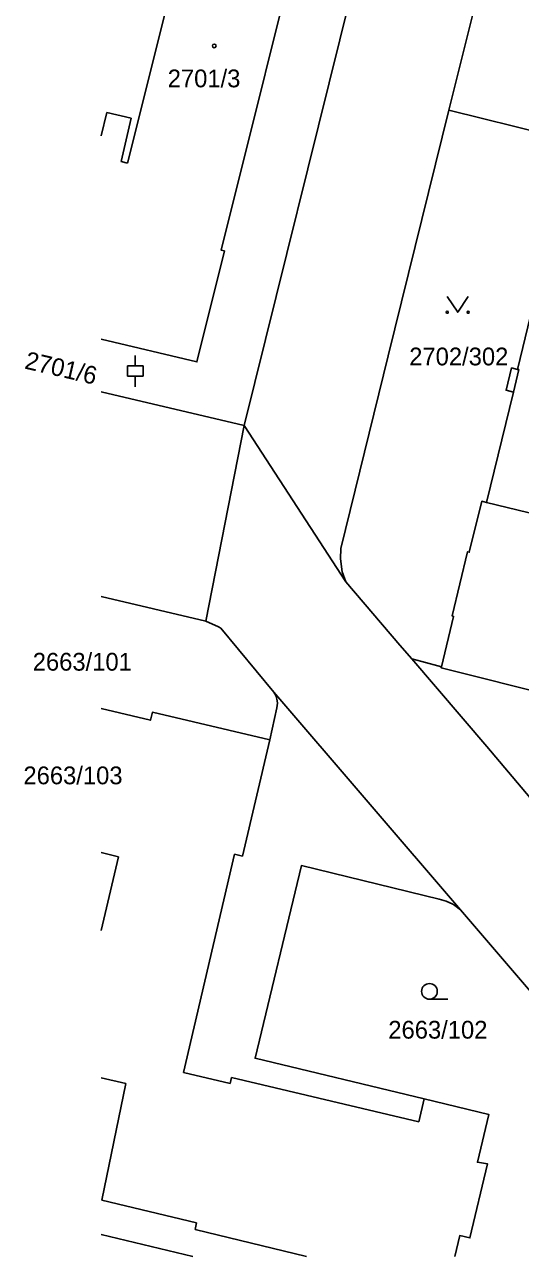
# Model space of a CAD drawing. Extents: x -496682 to -495776, y -1088797 to -1088018.
# Drawn here: x -496681.5 to -496634.1, y -1088569.4 to -1088451.6 of the extents above; entities that cross this region are included whole.
import ezdxf

# ---------------------------------------------------------------- set-up
doc = ezdxf.new("R2010")
doc.units = 0
for name, color, linetype in [('Hranice parcel', 7, 'Continuous'), ('Parcelní čísla', 7, 'Continuous'), ('Vnitřní kresba', 7, 'Continuous'), ('Značky budov', 7, 'Continuous'), ('Značky kultur', 7, 'Continuous')]:
    doc.layers.add(name, color=color, linetype=linetype)

msp = doc.modelspace()

# ---------------------------------------------------------------- linework, layer by layer
at = {"layer": 'Hranice parcel'}
for p, q in [((-496640.95, -1088459.81), (-496628.55, -1088409.94)), ((-496660.52, -1088489.98), (-496645.25, -1088428.29)), ((-496629.09, -1088462.74), (-496640.95, -1088459.81)), ((-496660.52, -1088489.98), (-496674.2, -1088486.74)), ((-496664.18, -1088508.68), (-496660.52, -1088489.98)), ((-496660.52, -1088489.98), (-496650.79, -1088504.94)), ((-496625.56, -1088500.2), (-496637.35, -1088497.34)), ((-496674.2, -1088506.32), (-496664.18, -1088508.68)), ((-496657.68, -1088515.47), (-496662.75, -1088509.37)), ((-496639.82, -1088536.3), (-496657.68, -1088515.47)), ((-496627.27, -1088550.98), (-496639.82, -1088536.3))]:
    msp.add_line(p, q, dxfattribs=at)
for points in [[(-496674.2, -1088481.71), (-496665.05, -1088483.89), (-496662.42, -1088473.27), (-496662.72, -1088473.21), (-496654.28, -1088439.31), (-496654, -1088439.38), (-496650.83, -1088426.78), (-496645.25, -1088428.29)], [(-496650.79, -1088504.94), (-496651.14, -1088503.97), (-496651.32, -1088502.72), (-496651.27, -1088501.75), (-496646.76, -1088483.31), (-496640.95, -1088459.81)], [(-496637.35, -1088497.34), (-496634.78, -1088486.77), (-496635.48, -1088486.6), (-496634.95, -1088484.46), (-496634.38, -1088484.6), (-496631.65, -1088473.31)], [(-496641.66, -1088513.05), (-496640.49, -1088508.23), (-496640.63, -1088508.19), (-496639.16, -1088502.05), (-496638.99, -1088502.09), (-496637.8, -1088497.21), (-496637.35, -1088497.34)], [(-496644.5, -1088512.3), (-496645.64, -1088510.97), (-496650.79, -1088504.94)], [(-496662.75, -1088509.37), (-496662.98, -1088509.24), (-496664.18, -1088508.68)], [(-496621.83, -1088538.93), (-496627.8, -1088531.94), (-496637.3, -1088520.68), (-496644.5, -1088512.3)], [(-496644.5, -1088512.3), (-496643.54, -1088512.55), (-496641.66, -1088513.05)], [(-496619.55, -1088518.48), (-496630.64, -1088516.04), (-496630.61, -1088515.92), (-496641.69, -1088513.15), (-496641.66, -1088513.05)], [(-496657.39, -1088516.99), (-496657.35, -1088516.54), (-496657.37, -1088516.31), (-496657.48, -1088515.87), (-496657.68, -1088515.47)], [(-496674.2, -1088517.05), (-496669.49, -1088518.17), (-496669.31, -1088517.4), (-496658.07, -1088520.03), (-496657.39, -1088516.99)], [(-496641.88, -1088535.27), (-496655.05, -1088532.06), (-496659.48, -1088550.5), (-496643.3, -1088554.38), (-496637.13, -1088555.87), (-496638.22, -1088560.45), (-496637.25, -1088560.61), (-496638.93, -1088567.68), (-496639.91, -1088567.46), (-496640.39, -1088569.45)], [(-496639.82, -1088536.3), (-496640.39, -1088535.89), (-496640.58, -1088535.77), (-496641.21, -1088535.48), (-496641.88, -1088535.27)], [(-496674.2, -1088567.37), (-496665.44, -1088569.45)]]:
    msp.add_lwpolyline(points, dxfattribs=at)
at = {"layer": 'Vnitřní kresba'}
for p, q in [((-496671.69, -1088464.87), (-496666.18, -1088442.82)), ((-496674.2, -1088462.26), (-496673.67, -1088460.03)), ((-496673.67, -1088460.03), (-496671.33, -1088460.58)), ((-496671.33, -1088460.58), (-496672.3, -1088464.73)), ((-496672.3, -1088464.73), (-496671.69, -1088464.87)), ((-496634.26, -1088484.62), (-496634.78, -1088486.77)), ((-496634.38, -1088484.6), (-496634.26, -1088484.62)), ((-496660.69, -1088531.17), (-496658.07, -1088520.03)), ((-496674.2, -1088530.83), (-496672.54, -1088531.23)), ((-496672.54, -1088531.23), (-496674.2, -1088538.29)), ((-496666.34, -1088551.87), (-496661.44, -1088530.99)), ((-496661.44, -1088530.99), (-496660.69, -1088531.17)), ((-496661.88, -1088552.92), (-496666.34, -1088551.87)), ((-496674.2, -1088552.36), (-496671.86, -1088552.91)), ((-496671.86, -1088552.91), (-496674.15, -1088564.06)), ((-496661.74, -1088552.35), (-496661.88, -1088552.92)), ((-496643.82, -1088556.57), (-496661.74, -1088552.35)), ((-496643.3, -1088554.38), (-496643.82, -1088556.57)), ((-496674.15, -1088564.06), (-496665.08, -1088566.24)), ((-496665.08, -1088566.24), (-496665.2, -1088566.88)), ((-496665.2, -1088566.88), (-496654.57, -1088569.45))]:
    msp.add_line(p, q, dxfattribs=at)
at = {"layer": 'Značky budov'}
msp.add_circle((-496663.39, -1088453.66), 0.175, dxfattribs=at)
at = {"layer": 'Značky kultur'}
for p, q in [((-496670.94, -1088484.26), (-496670.94, -1088483.26)), ((-496671.69, -1088484.26), (-496670.19, -1088484.26)), ((-496671.69, -1088485.26), (-496671.69, -1088484.26)), ((-496670.19, -1088485.26), (-496670.19, -1088484.26)), ((-496671.69, -1088485.26), (-496670.19, -1088485.26)), ((-496670.94, -1088486.26), (-496670.94, -1088485.26)), ((-496642.8, -1088544.85), (-496641.05, -1088544.85))]:
    msp.add_line(p, q, dxfattribs=at)
msp.add_lwpolyline([(-496641.1, -1088477.64), (-496640.1, -1088479.14), (-496639.1, -1088477.64)], dxfattribs=at)
for centre, radius in [((-496641.1, -1088479.14), 0.1), ((-496639.1, -1088479.14), 0.1), ((-496642.8, -1088544.1), 0.75)]:
    msp.add_circle(centre, radius, dxfattribs=at)

# ---------------------------------------------------------------- texts
at = {"layer": 'Parcelní čísla'}
for s, p in [('2701/3', (-496667.84, -1088457.62)), ('2702/302', (-496644.74, -1088484.22)), ('2663/101', (-496680.75, -1088513.42)), ('2663/103', (-496681.64, -1088524.29)), ('2663/102', (-496646.74, -1088548.62))]:
    msp.add_text(s, height=1.7, dxfattribs=at).set_placement(p)
msp.add_text('2701/6', height=1.7, rotation=347, dxfattribs=at).set_placement((-496681.61, -1088484.51))

doc.saveas('drawing.dxf')
